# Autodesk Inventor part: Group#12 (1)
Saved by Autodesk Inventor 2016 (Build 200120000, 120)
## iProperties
Created: 2016-09
Part Number: Group#12 (1)
Material: Generic
Document SubType Name: Modeling
Designer: Administrator
Appearance: Generic
Author: Administrator
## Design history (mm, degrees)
feature "Body1"
body "Solid1"
